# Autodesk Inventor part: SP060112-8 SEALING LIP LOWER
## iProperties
Created: 2011-07
Part Number: SP060112-8 SEALING LIP LOWER
Material: Rubber
Document SubType Name: Modeling
Designer: Administrator
Density: 0.93 g/cm^3
Mass: 66.2306 g
Surface Area: 631.866 cm^2
Volume: 71.2157 cm^3
Author: Administrator
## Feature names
1. Extrusion1
2. Extrusion3
